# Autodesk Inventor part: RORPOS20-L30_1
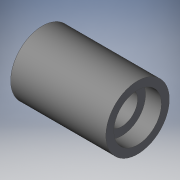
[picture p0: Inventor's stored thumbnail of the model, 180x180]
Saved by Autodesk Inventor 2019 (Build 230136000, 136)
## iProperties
Created: 2022-11
Part Number: RORPOS20-L30_1
Material: Generic
Catalog Web Link: www.cadenas.de
Description: RORPOS, RORPHS, RORPES, RORPJS, RORPSS, RORPQS, RORMCS_1-Plastic Roller -Milled/Straight-
Vendor: MISUMI
Document SubType Name: Modeling
Designer: psAdmin
Manufacturer: MISUMI
Mass: 6.08684 g
Surface Area: 34.5575 cm^2
Volume: 6.08684 cm^3
Density: 1 g/cm^3
Appearance: PSOLRGB-255-255-255
Category: PARTsolutions
Company: MISUMI
Title: RORPOS20-L30
Author: Cadenas PARTsolutions
Comments: Plastic Roller -Milled/Straight-
PSOL_IDENT_0: {$CADENAS_DATA/23d-libs/misumi/metric/53_rollers/rorpos.prj},227 {VTYP=3D},{NB=RORPOS20-L30_1},{LINA=
PSOL_IDENT_1: RORPOS20-L30},{NN=RORPOS, RORPHS, RORPES, RORPJS, RORPSS, RORPQS, RORMCS_1},{DATE=30.06.2021 13:26:5
PSOL_IDENT_2: 0},{GEOMDATE=18.05.2012 00:00:00},{VERSION=},{LINEID=10},{WBVAR=MAT,MATB,L},{WBNUMERIC=L}  {NB=RORPO
PSOL_IDENT_3: S20-L30_1},{LINA=RORPOS20-L30},{KT=DUMMY},{PN=RORPOS20-L30},{TYPE=RORPOS},{MAT=1},{ALT1=},{MATB=S},{
PSOL_IDENT_4: MATBALG= 'S', 'Steel', 'SS', 'Stainless Steel' },{NO=20},{NOM=20},{L=30},{L0=[15-100/1]},{BU=B696ZZx
PSOL_IDENT_5: 2},{BUN=696ZZ},{D=20},{D1=15},{DD=6},{B=5},{DDHH=10},{MATB1=Steel},{MATB2=52100 Bearing Steel}
NB: RORPOS20-L30_1
NN: RORPOS, RORPHS, RORPES, RORPJS, RORPSS, RORPQS, RORMCS_1
NT: Plastic Roller -Milled/Straight-
NBSYN: $PN._1
LINA: RORPOS20-L30
CATALOG: Misumi
PN: RORPOS20-L30
MAT: Polyacetal
MATB: Steel
NO: 20
L: 30
BU: B696ZZx2
D: 20
D1: 15
DD: 6
B: 5
DDHH: 10
SUPPLIER: MISUMI
ARTICLENO: RORPOS20-L30_1
BOMINFO: RORPOS20-L30
CREATOR: CADENAS GmbH
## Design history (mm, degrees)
sketch "Sketch_1"
  geometry: L1 (30, 0)-(0, 0); L2 (0, 7.5)-(5, 7.5); L3 (5, 7.5)-(5, 5); L4 (5, 5)-(25, 5); L5 (25, 5)-(25, 7.5); L6 (25, 7.5)-(30, 7.5); L7 (30, 7.5)-(30, 10); L8 (30, 10)-(0, 10); L9 (0, 10)-(0, 7.5)
  constraints: 18 end point
revolve "Revolution1" sketch "Sketch_1" stored, may be unused: angle "d0" = 360 deg
node "body_to_B_L__XY"
node "body_to_B_L__YZ"
node "body_to_B_L__ZX"
node "body_to_B_L__X"
node "body_to_B_L__Y"
node "body_to_B_L__Z"
node "body_to_B_L__Center"
node "body_to_B_R__XY"
node "body_to_B_R__YZ"
node "body_to_B_R__ZX"
node "body_to_B_R__X"
node "body_to_B_R__Y"
node "body_to_B_R__Z"
node "body_to_B_R__Center"
body "Solid1"
other parameters: "d1" = 0, "d2" = 0
